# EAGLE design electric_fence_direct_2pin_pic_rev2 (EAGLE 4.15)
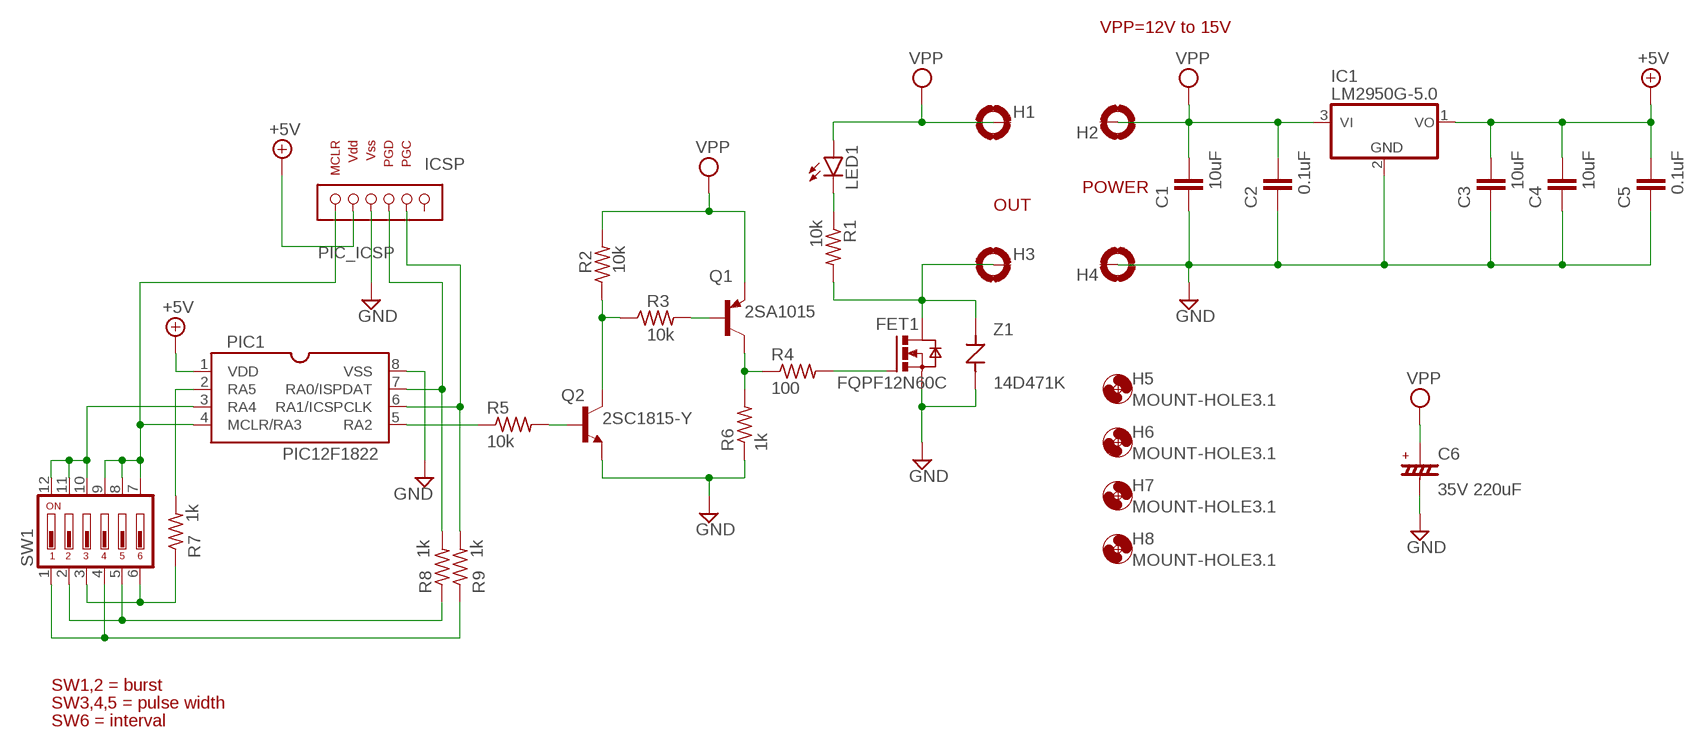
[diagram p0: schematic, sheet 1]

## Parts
C1  10uF  C-EU050-024X044_OLMX  [C050-024X044_OLMX]
C2  0.1uF  C-EU025-024X044_OLMX  [C025-024X044_OLMX]
C3  10uF  C-EU050-024X044_OLMX  [C050-024X044_OLMX]
C4  10uF  C-EU050-024X044_OLMX  [C050-024X044_OLMX]
C5  0.1uF  C-EU025-024X044_OLMX  [C025-024X044_OLMX]
C6  35V 220uF  CC3.0_D8.0  [C]
FET1  FQPF12N60C  IRF512HV  [TO-220HV]
H1  MOUNT-PAD-ROUND3.0-NOLING  [3,0-PAD-NOLING]
H2  MOUNT-PAD-ROUND3.0-NOLING  [3,0-PAD-NOLING]
H3  MOUNT-PAD-ROUND3.0-NOLING  [3,0-PAD-NOLING]
H4  MOUNT-PAD-ROUND3.0-NOLING  [3,0-PAD-NOLING]
H5  MOUNT-HOLE3.1  [3.1-HOLL]
H6  MOUNT-HOLE3.1  [3.1-HOLL]
H7  MOUNT-HOLE3.1  [3.1-HOLL]
H8  MOUNT-HOLE3.1  [3.1-HOLL]
IC1  LM2950G-5.0  78TO92INLINE  [TO-92INLINE]
ICSP  PIC_ICSP  [PIC_ICSP]
LED1  LED5MM_OLMX  [LED5MM_OLMX]
PIC1  PIC12F1822  PIC12DIL8  [DIL8_OLMX]
Q1  2SA1015  BC636-PNP-TO92-BCE_OLMX  [TO92-BCE_OLMX]
Q2  2SC1815-Y  BC635-NPN-TO92-BCE_OLMX  [TO92-BCE_OLMX]
R1  10k  R-US_0204/5_OLMX  [0204/5_OLMX]
R2  10k  R-US_0204/5_OLMX  [0204/5_OLMX]
R3  10k  R-US_0204/5_OLMX  [0204/5_OLMX]
R4  100  R-US_0204/5_OLMX  [0204/5_OLMX]
R5  10k  R-US_0204/5_OLMX  [0204/5_OLMX]
R6  1k  R-US_0204/5_OLMX  [0204/5_OLMX]
R7  1k  R-US_0204/5_OLMX  [0204/5_OLMX]
R8  1k  R-US_0204/5_OLMX  [0204/5_OLMX]
R9  1k  R-US_0204/5_OLMX  [0204/5_OLMX]
SW1  DS06_OLMX  [DS-06_OLMX]
Z1  14D471K  ZNR14MM  [ZNR14MM]

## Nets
+5V: C3.2 C4.2 C5.2 IC1.1(VO) ICSP.VDD PIC1.1(VDD)
GND [power]: C1.1 C2.1 C3.1 C4.1 C5.1 C6.P$2(MINUS) FET1.3(S) H4.B3,0(MOUNT) IC1.2(GND) ICSP.VSS PIC1.8(VSS) Q2.E R6.1 Z1.P$2
N$1: PIC1.2(RA5) R7.2
N$2: Q2.B R5.2
N$3: FET1.1(G) R4.2
N$4: R8.1 SW1.2 SW1.5
N$6 [power]: Q1.C R4.1 R6.2
N$7: LED1.K(C) R1.1
N$8: Q1.B R3.2
N$9: ICSP.MCLR PIC1.4(MCLR/RA3) SW1.7 SW1.8 SW1.9
N$10: R9.1 SW1.1 SW1.4
N$11: R7.1 SW1.3 SW1.6
N$12: Q2.C R2.1 R3.1
N$13: ICSP.PGD PIC1.7(RA0/ISPDAT) R8.2
N$14: PIC1.3(RA4) SW1.10 SW1.11 SW1.12
N$15: PIC1.5(RA2) R5.1
N$16: ICSP.PGC PIC1.6(RA1/ICSPCLK) R9.2
OUT-: FET1.2(D) H3.B3,0(MOUNT) R1.2 Z1.P$1
VPP [power]: C1.2 C2.2 C6.P$1(PLUS) H1.B3,0(MOUNT) H2.B3,0(MOUNT) IC1.3(VI) LED1.A Q1.E R2.2
Unconnected: ICSP.NC

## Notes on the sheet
- VPP=12V to 15V
- POWER
- OUT
- SW1,2 = burst
- SW3,4,5 = pulse width
- SW6 = interval

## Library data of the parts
C1-C5 = rcl:C-EU: CAPACITOR, European symbol
C6 = 002mylib:C
FET1 = transistor-power:IRF512: N-CHANNEL MOS FET
H1-H4 = holes:MOUNT-PAD-ROUND: MOUNTING PAD, round
H5-H8 = holes:MOUNT-HOLE: MOUNTING HOLE with drill center marker
IC1 = linear:78*: Positive VOLTAGE REGULATOR Source: http://cache.national.com/ds/LM/LM78L05.pdf http://www.fairchildsemi.com/ds/LM/LM7805.pdf
ICSP = 001mylib:PIC_ICSP
LED1 = led:LED: LED
PIC1 = microchip:PIC12
Q1 = transistor:*-PNP-: PNP Transistror
Q2 = transistor:*-NPN-: NPN Transistror
R1-R9 = rcl:R-US_: RESISTOR, American symbol
SW1 = switch-dil:DS06: DIL/CODE SWITCH
Z1 = 001mylib:ZNR

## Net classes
0 default: width 0.508 mm, drill 0.406 mm
1 power: width 0.635 mm, drill 0.508 mm

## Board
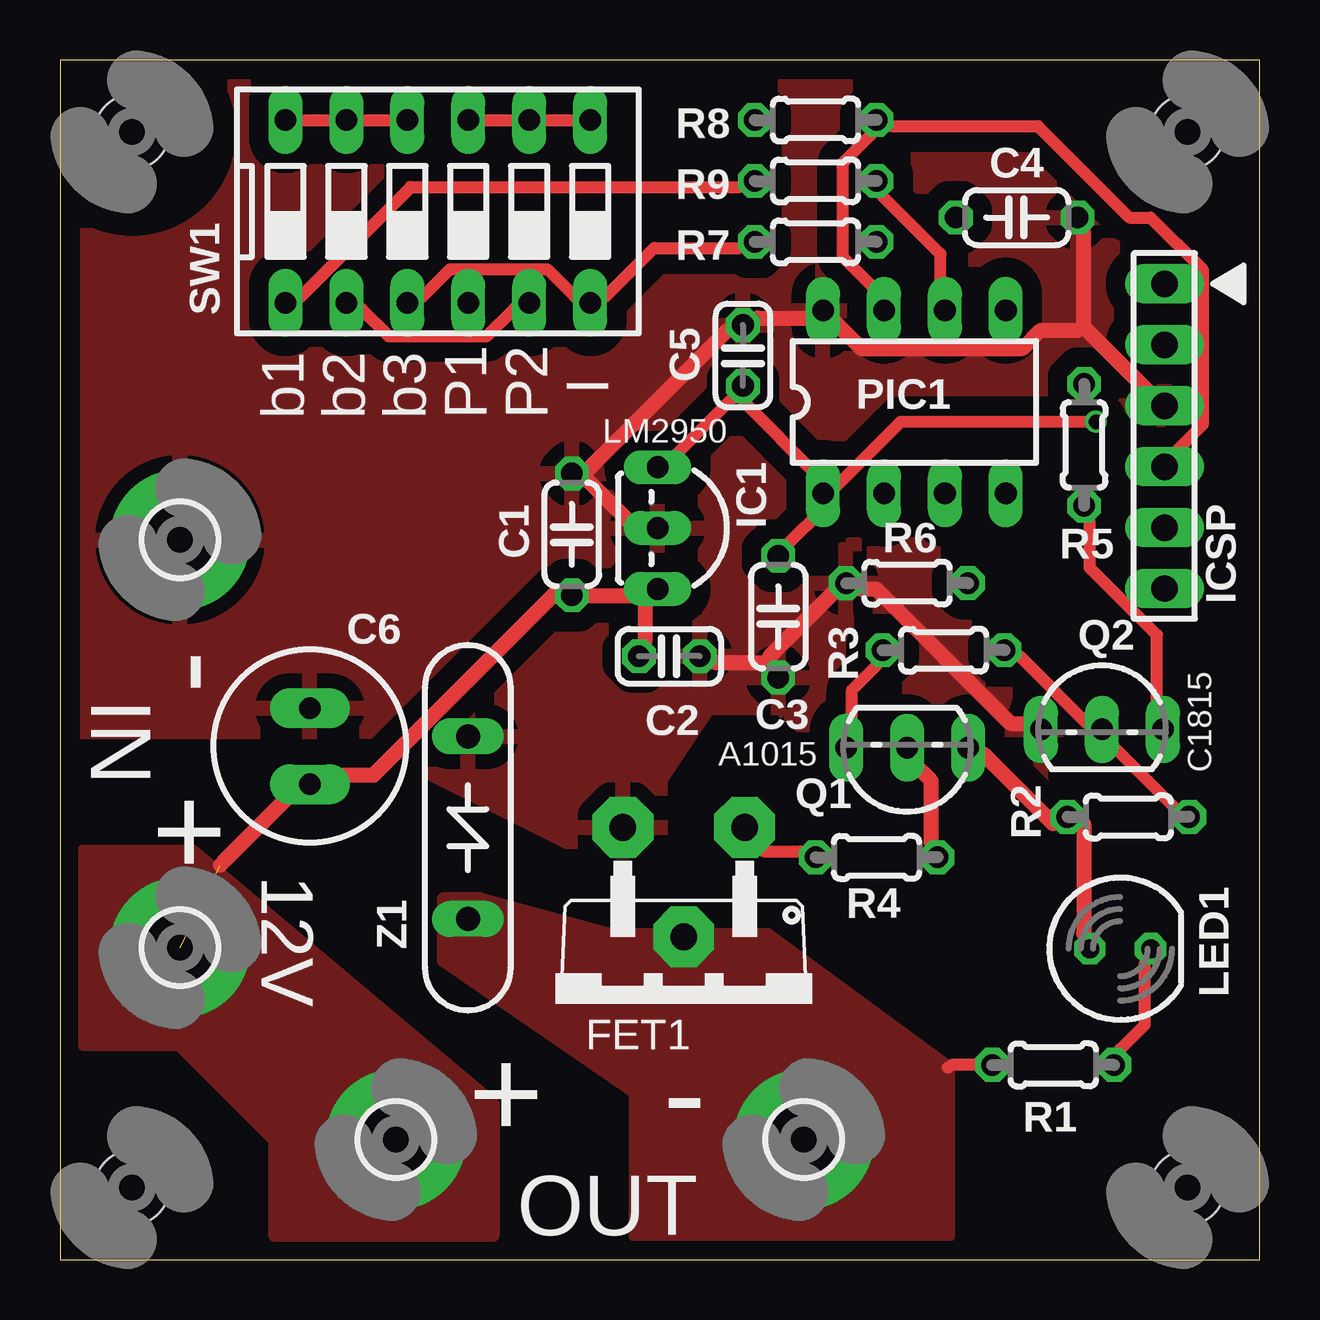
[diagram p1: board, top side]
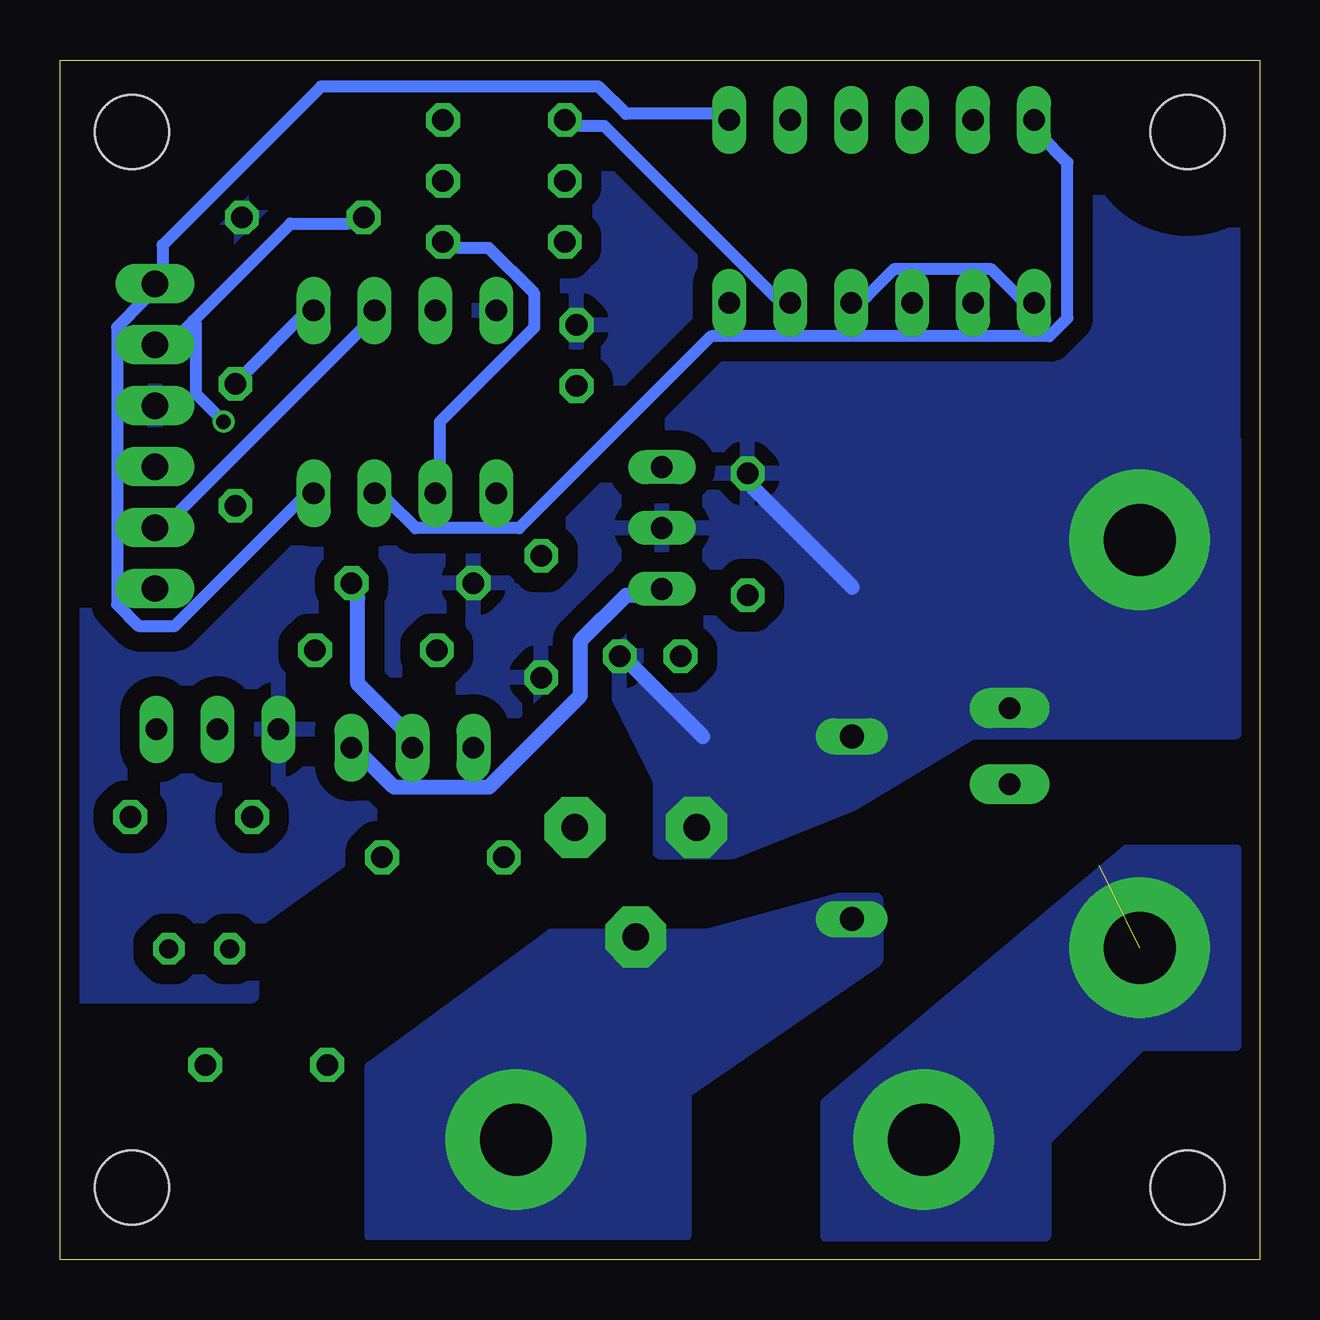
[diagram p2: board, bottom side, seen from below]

Size 50 x 50 mm. Coordinates in mm from the lower left corner, seen from the top.
Outline: 0,0 50,0 50,50 0,50 0,0
Copper layers (1*16): Top 0.035mm / dielectric 1.5mm / Bottom 0.035mm
Design rules "FUSION_IIZUKA_STANDARD": minimum track width 6mil, minimum drill 0.6mm, track to track 8mil, track to pad 8mil, pad to pad 8mil, via to via 8mil, smd to smd 0mil, copper to edge 30mil, drill to drill 10mil, minimum pad ring 10mil, minimum via ring 6mil, stop-mask expansion 2mil, vias tented up to drill 100mil, thermal gap 24mil

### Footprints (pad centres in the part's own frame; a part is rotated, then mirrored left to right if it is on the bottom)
C050-024X044_OLMX = drill 0.9 octagon: 1 -2.54,0; 2 2.54,0
C025-024X044_OLMX = drill 0.9 octagon: 1 -1.27,0; 2 1.27,0
C = drill 0.9 pad 1.676 long: P$1 1.27,0; P$2 -1.905,0
TO-220HV = drill 1.118 pad 2.54 octagon: 1 -2.54,-1.016; 2 0,3.556; 3 2.54,-1.016
3,0-PAD-NOLING = drill 3 pad 5.842 round: B3,0 0,0
3.1-HOLL = hole 3.1: 0,0
TO-92INLINE = drill 0.9 long: 1 -2.54,0; 2 0,0; 3 2.54,0
PIC_ICSP = drill 1.1 long: MCLR -6.35,0; NC 6.35,0; PGC 3.81,0; PGD 1.27,0; VDD -3.81,0; VSS -1.27,0
LED5MM_OLMX = drill 0.8 octagon: A -1.27,0; K 1.27,0
DIL8_OLMX = drill 0.9 long: 1 -3.81,-3.81; 2 -1.27,-3.81; 3 1.27,-3.81; 4 3.81,-3.81; 5 3.81,3.81; 6 1.27,3.81; 7 -1.27,3.81; 8 -3.81,3.81
TO92-BCE_OLMX = drill 0.9 long: B 2.54,0; C 0,0; E -2.54,0
0204/5_OLMX = drill 0.9 octagon: 1 -2.54,0; 2 2.54,0
DS-06_OLMX = drill 0.9 long: 1 -6.35,-3.81; 2 -3.81,-3.81; 3 -1.27,-3.81; 4 1.27,-3.81; 5 3.81,-3.81; 6 6.35,-3.81; 7 6.35,3.81; 8 3.81,3.81; 9 1.27,3.81; 10 -1.27,3.81; 11 -3.81,3.81; 12 -6.35,3.81
ZNR14MM = drill 1 long: P$1 -3.81,0; P$2 3.81,0

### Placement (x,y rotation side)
C1  21.34,30.23 270 top
C2  25.4,25.15 180 top
C3  29.94,26.8 90 top
C4  39.88,43.43 180 top
C5  28.47,37.68 270 top
C6  10.41,21.08 270 top
FET1  26,17 180 top
H1  5,13 0 top
H2  14,5 0 top
H3  31,5 0 top
H4  5,30 0 top
H5  3,47 0 top
H6  47,47 0 top
H7  3,3 0 top
H8  47,3 0 top
IC1  24.91,30.49 270 top
ICSP  46.03,34.32 270 top
LED1  44.2,12.95 0 top
PIC1  35.62,35.75 0 top
Q1  35.31,21.34 180 top
Q2  43.43,22.1 0 top
R1  41.4,8.11 180 top
R2  44.53,18.45 180 top
R3  36.83,25.4 180 top
R4  34.04,16.76 180 top
R5  42.69,33.96 270 top
R6  35.31,28.19 0 top
R7  31.5,42.42 0 top
R8  31.5,47.5 0 top
R9  31.5,44.96 0 top
SW1  15.75,43.69 0 top
Z1  17,18 90 top

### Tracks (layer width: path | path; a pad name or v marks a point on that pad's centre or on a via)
+5V  (via drill 0.6)
  Top 0.508: C3.2 30.35,29.84 31.75,31.24 PIC1.1 | IC1.1 25.53,33.4 28.07,35.94 C5.2 28.45,35.81 31.62,32.64 PIC1.1 | v43.18,34.92 35.05,34.92 32.38,32.26 PIC1.1
  Bottom 0.508: 44.45,39.12 45.21,38.35 ICSP.VDD | 44.45,39.12 40.39,43.18 37.97,43.18 C4.2 | v43.18,34.92 44.32,36.07 44.32,38.99 44.45,39.12
GND
  Top 0.635: 29.59,24.89 27.3,24.89 C2.1 | 29.59,24.89 C3.1 | 29.59,24.89 29.59,25.15 32.26,27.81 R6.1 33.4,27.94 34.04,27.94 39.62,22.35 40.26,22.35 Q2.E | 42.67,38.86 42.67,42.8 C4.1 | 42.67,38.86 45.47,36.07 ICSP.VSS | IC1.2 24.26,30.23 21.97,32.51 C1.1 21.97,32.89 27.81,38.73 C5.1 29.08,39.24 31.24,39.24 PIC1.8 32.26,39.12 33.4,37.97 40.13,37.97 40.89,38.73 42.42,38.73 42.67,38.86
  Bottom 0.635: C2.1 26.16,24.77 23.2,21.8 | 16.98,28.02 21.08,32.13 C1.1
  pour Bottom (isolate 0.61, no thermals): 1,34.03 11,34 25,20 25,17 22,17 17,19 12,22 1,22
  pour Bottom (isolate 0.813, rank 2): 0,50 50,50 50,11 42,11 42,14 28,24 27,24 25,20 11,34 0,34
  pour Top (isolate 0.813, rank 2): 0,50 50,50 50,11 42,11 42,13 30,23 27,23 25,20 25,17 22,17 12,22 0,22
N$1
  Bottom 0.508: PIC1.2 34.16,32.64 34.16,34.92 30.23,38.86 30.23,40.26 32.13,42.16 33.4,42.16 R7.2
N$2
  Top 0.508: Q2.B 45.72,22.73 45.72,26.04 42.93,28.83 42.93,30.73 R5.2
N$3
  Top 0.508: R4.2 30.86,17.02 29.34,17.02 FET1.1
N$4
  Top 0.508: SW1.2 12.57,39.62 13.72,38.48 17.78,38.48 18.92,39.62 SW1.5
  Bottom 0.508: R8.1 28.32,47.24 27.3,47.24 20.19,40.13 SW1.5
N$6
  Top 0.635: R4.1 36.32,17.4 36.32,19.94 35.56,20.7 Q1.C
  Bottom 0.635: R6.2 37.59,27.56 37.59,24 35.56,21.97 Q1.C
N$7
  Top 0.508: LED1.K 45.21,12.32 45.21,9.78 44.2,8.76 R1.1
N$8
  Top 0.508: Q1.B 33.02,21.97 33.02,23.75 34.04,24.77 R3.2
N$9
  Top 0.508: SW1.9 SW1.8 SW1.7
  Bottom 0.508: PIC1.4 40.01,31.62 45.21,26.42 46.74,26.42 47.62,27.3 47.62,38.86 46.48,40.01 ICSP.MCLR 45.72,41.4 45.72,42.29 39.12,48.9 27.56,48.9 26.42,47.75 22.73,47.75 SW1.7
N$10
  Top 0.508: R9.1 28.32,44.7 14.61,44.7 10.03,40.13 SW1.1
  Bottom 0.508: SW1.1 10.03,40.13 11.18,41.27 15.24,41.27 16.38,40.13 SW1.4
N$11
  Top 0.508: SW1.3 15.11,40.13 16.26,41.27 20.32,41.27 21.46,40.13 SW1.6 22.73,40.13 24.77,42.16 28.32,42.16 R7.1
N$12
  Top 0.508: R3.1 40.01,25.15 42.8,22.35 Q2.C 43.69,21.59 46.48,18.8 R2.1
N$13
  Top 0.508: PIC1.7 34.16,40.26 32.64,41.78 32.64,45.72 33.78,46.86 R8.2 34.67,47.24 40.77,47.24 44.58,43.43 45.47,43.43 47.62,41.27 47.62,34.8 46.48,33.66 ICSP.PGD
N$14
  Top 0.508: SW1.12 SW1.11 SW1.10
  Bottom 0.508: PIC1.3 36.32,31.62 35.18,30.48 30.86,30.48 22.86,38.48 8.76,38.48 8,39.24 8,45.72 9.14,46.86 SW1.12
N$15
  Bottom 0.508: PIC1.5 40.01,39.24 42.29,36.96 R5.1
N$16
  Top 0.508: PIC1.6 36.7,40.26 36.7,41.91 34.29,44.32 R9.2
  Bottom 0.508: ICSP.PGC 45.34,30.86 37.21,38.99 PIC1.6
OUT-
  Top 0.508: R1.2 38.23,8.13 37.21,8.13 37,8
  pour Bottom (isolate 0.813, no thermals): 23,13.5 17.5,15 16,15 16,12.5 24,7 24,1 37,1 37,8 29.5,13.5
  pour Top (isolate 0.813, no thermals): 16,15 16,12.5 24,7 24,1 37,1 37,8 29.5,13.5 23,13.5 17.5,15
VPP  (1 unrouted)
  Top 0.635: LED1.A 42.67,13.59 42.67,18.16 R2.2 41.4,18.16 38.48,21.08 Q1.E | 6.68,16.43 6.86,16.64 9.65,19.43 C6.P$1 11.18,20.19 13.08,20.19 20.7,27.81 C1.2 24.13,27.69 24.38,27.56 | 24.38,27.56 24.38,25.78 C2.2 | 24.38,27.56 IC1.3
  Bottom 0.635: Q1.E 37.34,20.95 36.07,19.68 32.13,19.68 28.32,23.5 28.32,25.78 26.42,27.69 25.53,27.69 IC1.3
  pour Bottom (isolate 0.61, no thermals): 1,17 1,9 5,9 9,5 9,1 12,1 11,1 18,1 18,6.5 5.5,17
  pour Top (no thermals): 1,17 5.5,17 18,6.5 18,1 9,1 9,5 5,9 1,9

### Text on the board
tPlace: I | b1 | b2 | b3 | P1 | P2 | LM2950 | - | IN | A1015 | C1815 | + | 12V | + | - | OUT
_tNames: R8 | C4 | R9 | R7 | SW1 | C5 | PIC1 | C1 | R6 | ICSP | IC1 | R5 | C6 | R3 | Q2 | C2 | C3 | Q1 | R2 | R4 | Z1 | LED1 | FET1 | R1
